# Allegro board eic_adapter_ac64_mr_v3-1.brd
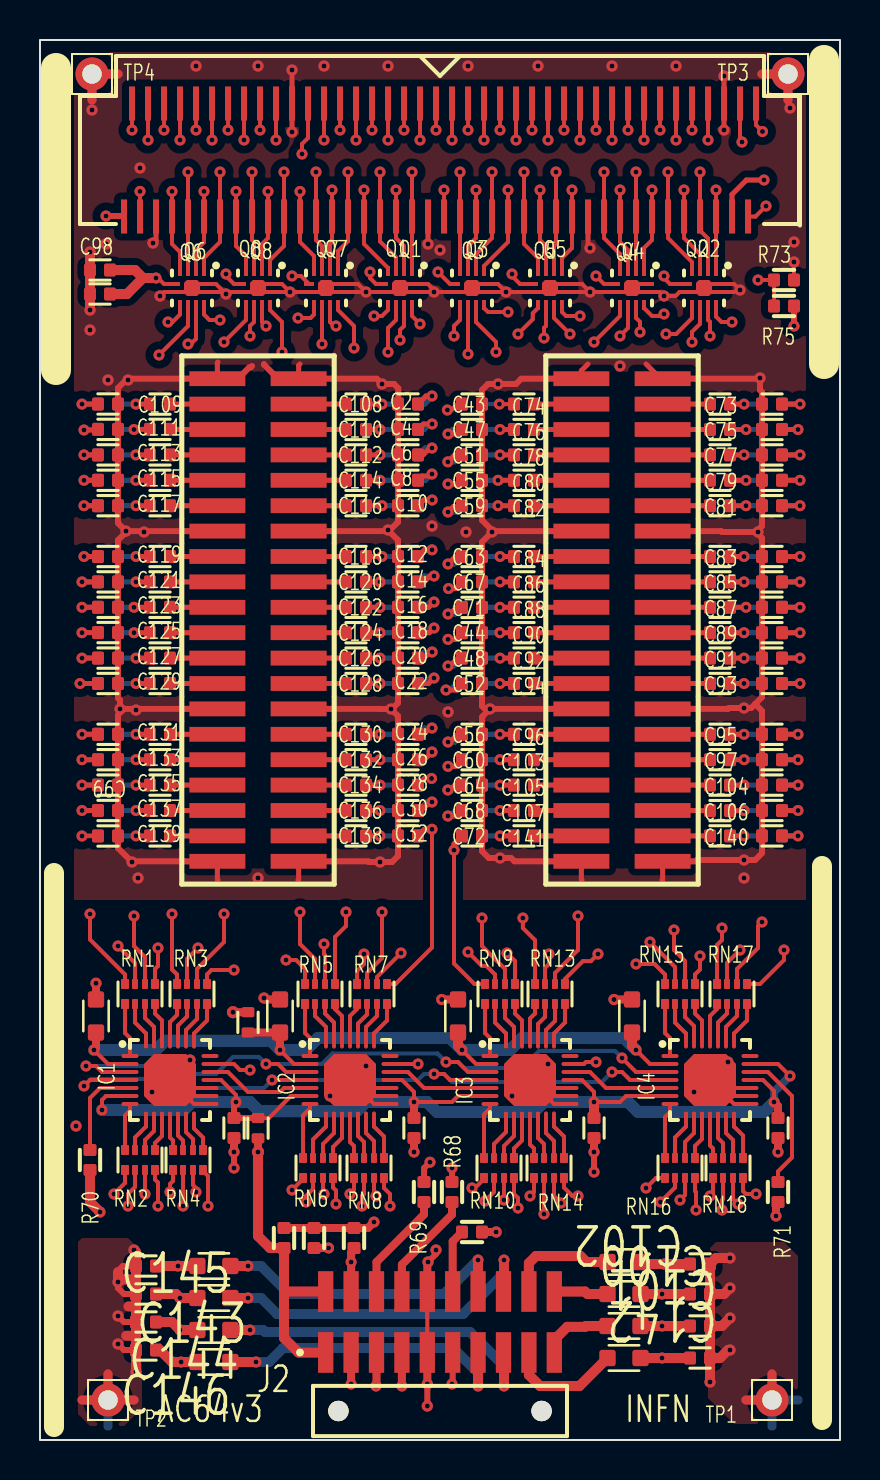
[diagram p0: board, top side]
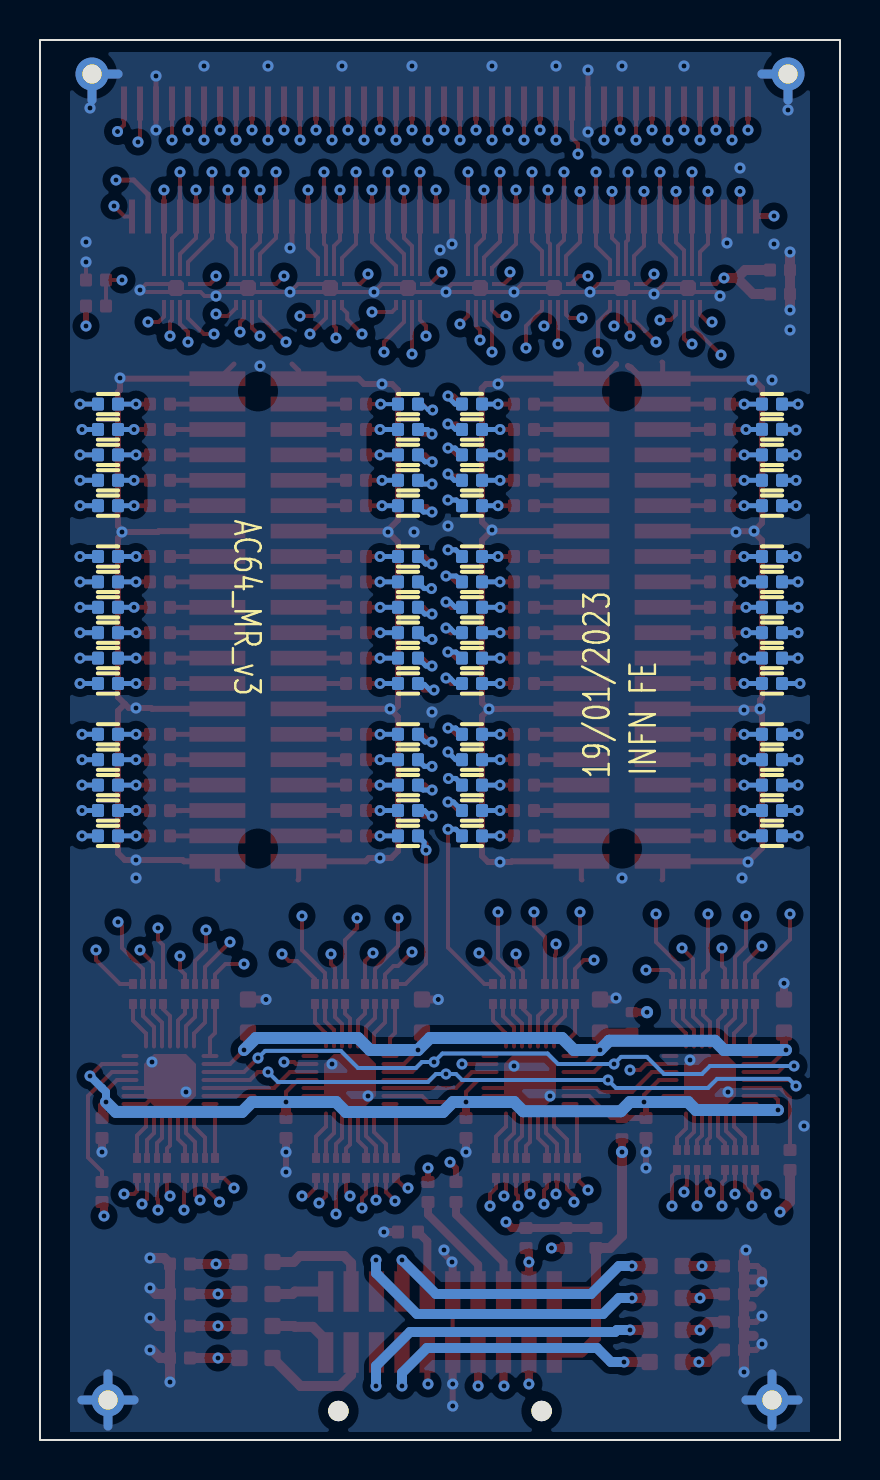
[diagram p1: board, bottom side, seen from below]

Outline 40 x 70 mm; copper layers: TOP, LAYER_1, LAYER_2, LAYER_3, LAYER_4, LAYER_5, LAYER_6, LAYER_7, LAYER_8, BOTTOM. Coordinates in mm from the lower left corner of the outline.
Outline path: rectangle 0,0 40,70

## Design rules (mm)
constraint set DEFAULT: pair gap 0.2

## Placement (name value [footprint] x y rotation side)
C1  100nF  [SM_C_0402_R]  3 57.3 0 top
C2  100nF  [SM_C_0402_R]  18.4 51.8 0 top
C3  100nF  [SM_C_0402_R]  3.4 51.8 180 top
C4  100nF  [SM_C_0402_R]  18.4 50.52 0 top
C5  100nF  [SM_C_0402_R]  3.4 50.53 180 top
C6  100nF  [SM_C_0402_R]  18.4 49.26 0 top
C7  100nF  [SM_C_0402_R]  3.4 49.26 180 top
C8  100nF  [SM_C_0402_R]  18.4 47.98 0 top
C9  100nF  [SM_C_0402_R]  3.4 47.98 180 top
C10  100nF  [SM_C_0402_R]  18.4 46.72 0 top
C11  100nF  [SM_C_0402_R]  3.4 46.72 180 top
C12  100nF  [SM_C_0402_R]  18.4 44.17 0 top
C13  100nF  [SM_C_0402_R]  3.4 44.17 180 top
C14  100nF  [SM_C_0402_R]  18.4 42.91 0 top
C15  100nF  [SM_C_0402_R]  3.4 42.91 180 top
C16  100nF  [SM_C_0402_R]  18.4 41.63 0 top
C17  100nF  [SM_C_0402_R]  3.4 41.63 180 top
C18  100nF  [SM_C_0402_R]  18.4 40.37 0 top
C19  100nF  [SM_C_0402_R]  3.4 40.37 180 top
C20  100nF  [SM_C_0402_R]  18.4 39.09 0 top
C21  100nF  [SM_C_0402_R]  3.4 39.09 180 top
C22  100nF  [SM_C_0402_R]  18.4 37.83 0 top
C23  100nF  [SM_C_0402_R]  3.4 37.83 180 top
C24  100nF  [SM_C_0402_R]  18.4 35.28 0 top
C25  100nF  [SM_C_0402_R]  3.4 35.28 180 top
C26  100nF  [SM_C_0402_R]  18.4 34.02 0 top
C27  100nF  [SM_C_0402_R]  3.4 34.02 180 top
C28  100nF  [SM_C_0402_R]  18.4 32.74 0 top
C29  100nF  [SM_C_0402_R]  3.4 32.74 180 top
C30  100nF  [SM_C_0402_R]  18.4 31.47 0 top
C31  100nF  [SM_C_0402_R]  3.4 31.48 180 top
C32  100nF  [SM_C_0402_R]  18.4 30.2 0 top
C33  1uF  [SM_C_0603]  20.9 21.2 270 top
C34  100nF  [SM_C_0402_R]  18.7 15.6 90 top
C35  100nF  [SM_C_0402_R]  9.7 15.6 90 top
C36  1uF  [SM_C_0603]  12 21.2 270 top
C37  1uF  [SM_C_0603]  29.6 21.2 270 top
C38  1uF  [SM_C_0603]  2.8 21.2 270 top
C39  100nF  [SM_C_0402_R]  36.6 51.8 0 top
C40  100nF  [SM_C_0402_R]  27.7 15.6 90 top
C41  100nF  [SM_C_0402_R]  36.9 15.6 90 top
C42  100nF  [SM_C_0402_R]  36.6 40.37 0 top
C43  100nF  [SM_C_0402_R]  21.6 51.8 180 top
C44  100nF  [SM_C_0402_R]  21.6 40.37 180 top
C45  100nF  [SM_C_0402_R]  36.6 50.52 0 top
C46  100nF  [SM_C_0402_R]  36.6 39.09 0 top
C47  100nF  [SM_C_0402_R]  21.6 50.52 180 top
C48  100nF  [SM_C_0402_R]  21.6 39.09 180 top
C49  100nF  [SM_C_0402_R]  36.6 49.26 0 top
C50  100nF  [SM_C_0402_R]  36.6 37.83 0 top
C51  100nF  [SM_C_0402_R]  21.6 49.26 180 top
C52  100nF  [SM_C_0402_R]  21.6 37.83 180 top
C53  100nF  [SM_C_0402_R]  36.6 47.98 0 top
C54  100nF  [SM_C_0402_R]  36.6 35.28 0 top
C55  100nF  [SM_C_0402_R]  21.6 47.98 180 top
C56  100nF  [SM_C_0402_R]  21.6 35.28 180 top
C57  100nF  [SM_C_0402_R]  36.6 46.72 0 top
C58  100nF  [SM_C_0402_R]  36.6 34.02 0 top
C59  100nF  [SM_C_0402_R]  21.6 46.72 180 top
C60  100nF  [SM_C_0402_R]  21.6 34.02 180 top
C61  100nF  [SM_C_0402_R]  36.6 44.17 0 top
C62  100nF  [SM_C_0402_R]  36.6 32.74 0 top
C63  100nF  [SM_C_0402_R]  21.6 44.17 180 top
C64  100nF  [SM_C_0402_R]  21.6 32.74 180 top
C65  100nF  [SM_C_0402_R]  36.6 42.91 0 top
C66  100nF  [SM_C_0402_R]  36.6 31.48 0 top
C67  100nF  [SM_C_0402_R]  21.6 42.91 180 top
C68  100nF  [SM_C_0402_R]  21.6 31.48 180 top
C69  100nF  [SM_C_0402_R]  36.6 41.63 0 top
C70  100nF  [SM_C_0402_R]  36.6 30.2 0 top
C71  100nF  [SM_C_0402_R]  21.6 41.63 180 top
C72  100nF  [SM_C_0402_R]  21.6 30.2 180 top
C73  4.7nF  [SM_C_0402_R]  34 51.8 0 top
C74  4.7nF  [SM_C_0402_R]  24.2 51.8 180 top
C75  4.7nF  [SM_C_0402_R]  34 50.52 0 top
C76  4.7nF  [SM_C_0402_R]  24.2 50.52 180 top
C77  4.7nF  [SM_C_0402_R]  34 49.26 0 top
C78  4.7nF  [SM_C_0402_R]  24.2 49.26 180 top
C79  4.7nF  [SM_C_0402_R]  34 47.98 0 top
C80  4.7nF  [SM_C_0402_R]  24.2 47.98 180 top
C81  4.7nF  [SM_C_0402_R]  34 46.72 0 top
C82  4.7nF  [SM_C_0402_R]  24.2 46.72 180 top
C83  4.7nF  [SM_C_0402_R]  34 44.17 0 top
C84  4.7nF  [SM_C_0402_R]  24.2 44.17 180 top
C85  4.7nF  [SM_C_0402_R]  34 42.91 0 top
C86  4.7nF  [SM_C_0402_R]  24.2 42.91 180 top
C87  4.7nF  [SM_C_0402_R]  34 41.63 0 top
C88  4.7nF  [SM_C_0402_R]  24.2 41.63 180 top
C89  4.7nF  [SM_C_0402_R]  34 40.37 0 top
C90  4.7nF  [SM_C_0402_R]  24.2 40.37 180 top
C91  4.7nF  [SM_C_0402_R]  34 39.09 0 top
C92  4.7nF  [SM_C_0402_R]  24.2 39.09 180 top
C93  4.7nF  [SM_C_0402_R]  34 37.83 0 top
C94  4.7nF  [SM_C_0402_R]  24.2 37.83 180 top
C95  4.7nF  [SM_C_0402_R]  34 35.28 0 top
C96  4.7nF  [SM_C_0402_R]  24.2 35.28 180 top
C97  4.7nF  [SM_C_0402_R]  34 34.02 0 top
C98  100nF  [SM_C_0402_R]  3 58.5 0 top
C99  100nF  [SM_C_0402_R]  3.4 30.2 180 top
C100  100nF  [SM_C_0402_R]  33 7.3 180 top
C101  100nF  [SM_C_0402_R]  33 5.7 180 top
C102  100nF  [SM_C_0402_R]  33 8.8 180 top
C103  4.7nF  [SM_C_0402_R]  24.2 34.02 180 top
C104  4.7nF  [SM_C_0402_R]  34 32.74 0 top
C105  4.7nF  [SM_C_0402_R]  24.2 32.74 180 top
C106  4.7nF  [SM_C_0402_R]  34 31.47 0 top
C107  4.7nF  [SM_C_0402_R]  24.2 31.48 180 top
C108  4.7nF  [SM_C_0402_R]  15.8 51.8 0 top
C109  4.7nF  [SM_C_0402_R]  6 51.8 180 top
C110  4.7nF  [SM_C_0402_R]  15.8 50.52 0 top
C111  4.7nF  [SM_C_0402_R]  6 50.53 180 top
C112  4.7nF  [SM_C_0402_R]  15.8 49.26 0 top
C113  4.7nF  [SM_C_0402_R]  6 49.26 180 top
C114  4.7nF  [SM_C_0402_R]  15.8 47.98 0 top
C115  4.7nF  [SM_C_0402_R]  6 47.98 180 top
C116  4.7nF  [SM_C_0402_R]  15.8 46.72 0 top
C117  4.7nF  [SM_C_0402_R]  6 46.72 180 top
C118  4.7nF  [SM_C_0402_R]  15.8 44.17 0 top
C119  4.7nF  [SM_C_0402_R]  6 44.17 180 top
C120  4.7nF  [SM_C_0402_R]  15.8 42.91 0 top
C121  4.7nF  [SM_C_0402_R]  6 42.91 180 top
C122  4.7nF  [SM_C_0402_R]  15.8 41.63 0 top
C123  4.7nF  [SM_C_0402_R]  6 41.63 180 top
C124  4.7nF  [SM_C_0402_R]  15.8 40.37 0 top
C125  4.7nF  [SM_C_0402_R]  6 40.37 180 top
C126  4.7nF  [SM_C_0402_R]  15.8 39.09 0 top
C127  4.7nF  [SM_C_0402_R]  6 39.09 180 top
C128  4.7nF  [SM_C_0402_R]  15.8 37.83 0 top
C129  4.7nF  [SM_C_0402_R]  6 37.83 180 top
C130  4.7nF  [SM_C_0402_R]  15.8 35.28 0 top
C131  4.7nF  [SM_C_0402_R]  6 35.28 180 top
C132  4.7nF  [SM_C_0402_R]  15.8 34.02 0 top
C133  4.7nF  [SM_C_0402_R]  6 34.02 180 top
C134  4.7nF  [SM_C_0402_R]  15.8 32.74 0 top
C135  4.7nF  [SM_C_0402_R]  6 32.74 180 top
C136  4.7nF  [SM_C_0402_R]  15.8 31.48 0 top
C137  4.7nF  [SM_C_0402_R]  6 31.48 180 top
C138  4.7nF  [SM_C_0402_R]  15.8 30.2 0 top
C139  4.7nF  [SM_C_0402_R]  6 30.2 180 top
C140  4.7nF  [SM_C_0402_R]  34 30.2 0 top
C141  4.7nF  [SM_C_0402_R]  24.2 30.2 180 top
C142  100nF  [SM_C_0402_R]  33 4.1 180 top
C143  100nF  [SM_C_0402_R]  5.3 7.3 0 top
C144  100nF  [SM_C_0402_R]  5.3 5.9 0 top
C145  100nF  [SM_C_0402_R]  5.3 8.7 0 top
C146  100nF  [SM_C_0402_R]  5.3 4.5 0 top
IC1  AD5674RBCPZ-1  [QFN29P4X4X]  6.5 18 0 top
IC2  AD5674RBCPZ-1  [QFN29P4X4X]  15.5 18 0 top
IC3  AD5674RBCPZ-1  [QFN29P4X4X]  24.5 18 0 top
IC4  AD5674RBCPZ-1  [QFN29P4X4X]  33.5 18 0 top
J1  SAMTEC FTS-120-02-dv-a  [FTS-120-X-DV-A]  29.1 41 270 top
J2  CON20A  [SAMTEC_FTSH-110-01-F-DH-A]  20 5.9 180 top
J3  SAMTEC FTS-120-02-dv-a  [FTS-120-X-DV-A]  10.9 41 270 top
J4  CON80  [CONN_HIROSE_FH30-80S-04]  20 64 270 top
L1  BLM15AX102SN1D  [SM_L_0603_R]  29.2 7.3 180 top
L2  BLM15AX102SN1D  [SM_L_0402_R]  10.9 15.59 270 top
L3  BLM15AX102SN1D  [SM_L_0402_R]  10.4 20.88 90 top
L4  BLM15AX102SN1D  [SM_L_0603_R]  29.2 5.7 180 top
L5  BLM15AX102SN1D  [SM_L_0603_R]  29.2 8.9 180 top
L6  BLM15AX102SN1D  [SM_L_0603_R]  29.2 4.1 180 top
L7  BLM15AX102SN1D  [SM_L_0603_R]  8.69 7.1 0 top
L8  BLM15AX102SN1D  [SM_L_0603_R]  8.69 5.5 0 top
L9  BLM15AX102SN1D  [SM_L_0603_R]  8.69 8.7 0 top
L10  BLM15AX102SN1D  [SM_L_0603_R]  8.69 3.9 0 top
NOREF  -  []  29.1 41 0 top
NOREF#2  -  []  10.9 41 0 top
NOREF#3  -  []  0 70 0 top
NOREF#4  -  []  20 64 90 top
NOREF#5  -  []  0 64.3 0 top
NOREF#6  -  []  0 0 90 top
NOREF#7  -  []  29.1 41 90 top
NOREF#8  -  []  0 0 0 top
Q1  DMN1250UFEL-7  [QFN13P1_50X1_50]  18 57.6 270 top
Q2  DMN1250UFEL-7  [QFN13P1_50X1_50]  33.2 57.6 270 top
Q3  DMN1250UFEL-7  [QFN13P1_50X1_50]  21.6 57.6 270 top
Q4  DMN1250UFEL-7  [QFN13P1_50X1_50]  29.6 57.6 270 top
Q5  DMN1250UFEL-7  [QFN13P1_50X1_50]  25.5 57.6 270 top
Q6  DMN1250UFEL-7  [QFN13P1_50X1_50]  7.6 57.6 270 top
Q7  DMN1250UFEL-7  [QFN13P1_50X1_50]  14.3 57.6 270 top
Q8  DMN1250UFEL-7  [QFN13P1_50X1_50]  10.9 57.6 270 top
R1  470ohm  [SM_R_0402_R]  18.4 51.8 180 bottom
R3  470ohm  [SM_R_0402_R]  18.4 40.37 180 bottom
R5  0ohm  [SM_R_0402_R]  12.2 10.1 90 top
R6  4.7K  [SM_R_0402]  15.7 10.1 270 top
R7  4.7K  [SM_R_0402]  13.7 10.1 270 top
R8  470ohm  [SM_R_0402_R]  3.4 51.8 0 bottom
R10  470ohm  [SM_R_0402_R]  3.4 40.37 0 bottom
R12  470ohm  [SM_R_0402_R]  18.4 50.52 180 bottom
R14  470ohm  [SM_R_0402_R]  18.4 39.09 180 bottom
R16  470ohm  [SM_R_0402_R]  3.4 50.53 0 bottom
R18  470ohm  [SM_R_0402_R]  3.4 39.09 0 bottom
R20  470ohm  [SM_R_0402_R]  18.4 49.26 180 bottom
R22  470ohm  [SM_R_0402_R]  18.4 37.83 180 bottom
R24  470ohm  [SM_R_0402_R]  3.4 49.26 0 bottom
R26  470ohm  [SM_R_0402_R]  3.4 37.83 0 bottom
R28  470ohm  [SM_R_0402_R]  18.4 47.98 180 bottom
R30  470ohm  [SM_R_0402_R]  18.4 35.28 180 bottom
R32  470ohm  [SM_R_0402_R]  3.4 47.98 0 bottom
R34  470ohm  [SM_R_0402_R]  3.4 35.28 0 bottom
R36  470ohm  [SM_R_0402_R]  18.4 46.72 180 bottom
R38  470ohm  [SM_R_0402_R]  18.4 34.02 180 bottom
R40  470ohm  [SM_R_0402_R]  3.4 46.72 0 bottom
R42  470ohm  [SM_R_0402_R]  3.4 34.02 0 bottom
R44  470ohm  [SM_R_0402_R]  18.4 44.17 180 bottom
R46  470ohm  [SM_R_0402_R]  18.4 32.74 180 bottom
R48  470ohm  [SM_R_0402_R]  3.4 44.17 0 bottom
R50  470ohm  [SM_R_0402_R]  3.4 32.74 0 bottom
R52  470ohm  [SM_R_0402_R]  18.4 42.91 180 bottom
R54  470ohm  [SM_R_0402_R]  18.4 31.48 180 bottom
R56  470ohm  [SM_R_0402_R]  3.4 42.91 0 bottom
R58  470ohm  [SM_R_0402_R]  3.4 31.48 0 bottom
R60  470ohm  [SM_R_0402_R]  18.4 41.63 180 bottom
R62  470ohm  [SM_R_0402_R]  18.4 30.2 180 bottom
R64  470ohm  [SM_R_0402_R]  3.4 41.63 0 bottom
R66  470ohm  [SM_R_0402_R]  3.4 30.21 0 bottom
R68  47ohm  [SM_R_0402_R]  20.6 12.4 270 top
R69  47ohm  [SM_R_0402_R]  19.2 12.4 270 top
R70  47ohm  [SM_R_0402_R]  2.5 14 270 top
R71  47ohm  [SM_R_0402_R]  36.9 12.4 270 top
R72  470ohm  [SM_R_0402_R]  36.6 51.8 180 bottom
R73  4.7K  [SM_R_0402_R]  37.2 58 0 top
R74  0ohm  [SM_R_0402_R]  21.6 10.4 180 top
R75  100ohm  [SM_R_0402_R]  37.2 56.7 0 top
R81  470ohm  [SM_R_0402_R]  36.6 40.37 180 bottom
R83  470ohm  [SM_R_0402_R]  21.6 51.8 0 bottom
R85  470ohm  [SM_R_0402_R]  21.6 40.37 0 bottom
R87  470ohm  [SM_R_0402_R]  36.6 50.52 180 bottom
R89  470ohm  [SM_R_0402_R]  36.6 39.09 180 bottom
R91  470ohm  [SM_R_0402_R]  21.6 50.52 0 bottom
R93  470ohm  [SM_R_0402_R]  21.6 39.09 0 bottom
R95  470ohm  [SM_R_0402_R]  36.6 49.26 180 bottom
R97  470ohm  [SM_R_0402_R]  36.6 37.83 180 bottom
R99  470ohm  [SM_R_0402_R]  21.6 49.26 0 bottom
R101  470ohm  [SM_R_0402_R]  21.6 37.83 0 bottom
R103  470ohm  [SM_R_0402_R]  36.6 47.98 180 bottom
R105  470ohm  [SM_R_0402_R]  36.6 35.28 180 bottom
R107  470ohm  [SM_R_0402_R]  21.6 47.98 0 bottom
R109  470ohm  [SM_R_0402_R]  21.6 35.28 0 bottom
R111  470ohm  [SM_R_0402_R]  36.6 46.72 180 bottom
R113  470ohm  [SM_R_0402_R]  36.6 34.02 180 bottom
R115  470ohm  [SM_R_0402_R]  21.6 46.72 0 bottom
R117  470ohm  [SM_R_0402_R]  21.6 34.02 0 bottom
R119  470ohm  [SM_R_0402_R]  36.6 44.17 180 bottom
R121  470ohm  [SM_R_0402_R]  36.6 32.74 180 bottom
R123  470ohm  [SM_R_0402_R]  21.6 44.17 0 bottom
R125  470ohm  [SM_R_0402_R]  21.6 32.74 0 bottom
R127  470ohm  [SM_R_0402_R]  36.6 42.91 180 bottom
R129  470ohm  [SM_R_0402_R]  36.6 31.48 180 bottom
R131  470ohm  [SM_R_0402_R]  21.6 42.91 0 bottom
R133  470ohm  [SM_R_0402_R]  21.6 31.48 0 bottom
R135  470ohm  [SM_R_0402_R]  36.6 41.63 180 bottom
R137  470ohm  [SM_R_0402_R]  36.6 30.2 180 bottom
R139  470ohm  [SM_R_0402_R]  21.6 41.63 0 bottom
R141  470ohm  [SM_R_0402_R]  21.6 30.2 0 bottom
RN1  47ohm x 4  [ARRAY_CAY10-J4_8P]  5 22.3 0 top
RN2  47ohm x 4  [ARRAY_CAY10-J4_8P]  5 14 180 top
RN3  47ohm x 4  [ARRAY_CAY10-J4_8P]  7.6 22.3 0 top
RN4  47ohm x 4  [ARRAY_CAY10-J4_8P]  7.4 14 180 top
RN5  47ohm x 4  [ARRAY_CAY10-J4_8P]  14 22.3 0 top
RN6  47ohm x 4  [ARRAY_CAY10-J4_8P]  13.9 13.6 180 top
RN7  47ohm x 4  [ARRAY_CAY10-J4_8P]  16.6 22.3 0 top
RN8  47ohm x 4  [ARRAY_CAY10-J4_8P]  16.45 13.6 180 top
RN9  47ohm x 4  [ARRAY_CAY10-J4_8P]  23 22.3 0 top
RN10  47ohm x 4  [ARRAY_CAY10-J4_8P]  22.95 13.6 180 top
RN13  47ohm x 4  [ARRAY_CAY10-J4_8P]  25.5 22.3 0 top
RN14  47ohm x 4  [ARRAY_CAY10-J4_8P]  25.45 13.6 180 top
RN15  47ohm x 4  [ARRAY_CAY10-J4_8P]  32 22.3 0 top
RN16  47ohm x 4  [ARRAY_CAY10-J4_8P]  32 13.6 180 top
RN17  47ohm x 4  [ARRAY_CAY10-J4_8P]  34.6 22.3 0 top
RN18  47ohm x 4  [ARRAY_CAY10-J4_8P]  34.4 13.6 180 top
TP1  TP  [PIN]  36.6 2 0 top
TP2  TP  [PIN]  3.4 2 0 top
TP3  TP  [PIN]  37.4 68.3 0 top
TP4  TP  [PIN]  2.6 68.3 0 top

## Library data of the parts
C1-C72 C98-C102 C142-C146 = C-100nF
C73-C97 C103-C141 = C
IC1-IC4 = AD5674RBCPZ
J1 J3 = FTSH-120-03-F-DV
J2 = CON20A
J4 = CON80
L1-L10 = BEAD_SM0603
Q1-Q8 = DMN1250UFEL-7
R1 R3 R5-R8 R10 R12 R14 R16 R18 R20 R22 R24 R26 R28 R30 R32 R34 R36 R38 R40 R42 R44 R46 R48 R50 R52 R54 R56 R58 R60 R62 R64 R66 R68-R75 R81 R83 R85 R87 R89 R91 R93 R95 R97 R99 R101 R103 R105 R107 R109 R111 R113 R115 R117 R119 R121 R123 R125 R127 R129 R131 R133 R135 R137 R139 R141 = R
RN1-RN10 RN13-RN18 = RES_ISO8
TP1-TP4 = TP

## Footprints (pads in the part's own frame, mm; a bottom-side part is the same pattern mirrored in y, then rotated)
ARRAY_CAY10-J4_8P
  rrect 0.4x0.5 smd: 1(-0.75,-0.5) 4(0.75,-0.5) 5(0.75,0.5) 8(-0.75,0.5)
  rrect 0.3x0.5 smd: 2(-0.25,-0.5) 3(0.25,-0.5) 6(0.25,0.5) 7(-0.25,0.5)
CONN_HIROSE_FH30-80S-04
  rect 1.7x0.3 smd: 1(-2.825,15.8) 2(2.825,15.4) 3(-2.825,15) 4(2.825,14.6) 5(-2.825,14.2) 6(2.825,13.8) 7(-2.825,13.4) 8(2.825,13) 9(-2.825,12.6) 10(2.825,12.2) 11(-2.825,11.8) 12(2.825,11.4) 13(-2.825,11) 14(2.825,10.6) 15(-2.825,10.2) 16(2.825,9.8) 17(-2.825,9.4) 18(2.825,9) 19(-2.825,8.6) 20(2.825,8.2) 21(-2.825,7.8) 22(2.825,7.4) 23(-2.825,7) 24(2.825,6.6) 25(-2.825,6.2) 26(2.825,5.8) 27(-2.825,5.4) 28(2.825,5) 29(-2.825,4.6) 30(2.825,4.2) 31(-2.825,3.8) 32(2.825,3.4) 33(-2.825,3) 34(2.825,2.6) 35(-2.825,2.2) 36(2.825,1.8) 37(-2.825,1.4) 38(2.825,1) 39(-2.825,0.6) 40(2.825,0.2) 41(-2.825,-0.2) 42(2.825,-0.6) 43(-2.825,-1) 44(2.825,-1.4) 45(-2.825,-1.8) 46(2.825,-2.2) 47(-2.825,-2.6) 48(2.825,-3) 49(-2.825,-3.4) 50(2.825,-3.8) 51(-2.825,-4.2) 52(2.825,-4.6) 53(-2.825,-5) 54(2.825,-5.4) 55(-2.825,-5.8) 56(2.825,-6.2) 57(-2.825,-6.6) 58(2.825,-7) 59(-2.825,-7.4) 60(2.825,-7.8) 61(-2.825,-8.2) 62(2.825,-8.6) 63(-2.825,-9) 64(2.825,-9.4) 65(-2.825,-9.8) 66(2.825,-10.2) 67(-2.825,-10.6) 68(2.825,-11) 69(-2.825,-11.4) 70(2.825,-11.8) 71(-2.825,-12.2) 72(2.825,-12.6) 73(-2.825,-13) 74(2.825,-13.4) 75(-2.825,-13.8) 76(2.825,-14.2) 77(-2.825,-14.6) 78(2.825,-15) 79(-2.825,-15.4) 80(2.825,-15.8)
FTS-120-X-DV-A
  round 0 hole 1 unplated: (-11.43,0) (11.43,0)
  rect 0.737x2.794 smd: 1(-12.065,-2.032) 2(-12.065,2.032) 3(-10.795,-2.032) 4(-10.795,2.032) 5(-9.525,-2.032) 6(-9.525,2.032) 7(-8.255,-2.032) 8(-8.255,2.032) 9(-6.985,-2.032) 10(-6.985,2.032) 11(-5.715,-2.032) 12(-5.715,2.032) 13(-4.445,-2.032) 14(-4.445,2.032) 15(-3.175,-2.032) 16(-3.175,2.032) 17(-1.905,-2.032) 18(-1.905,2.032) 19(-0.635,-2.032) 20(-0.635,2.032) 21(0.635,-2.032) 22(0.635,2.032) 23(1.905,-2.032) 24(1.905,2.032) 25(3.175,-2.032) 26(3.175,2.032) 27(4.445,-2.032) 28(4.445,2.032) 29(5.715,-2.032) 30(5.715,2.032) 31(6.985,-2.032) 32(6.985,2.032) 33(8.255,-2.032) 34(8.255,2.032) 35(9.525,-2.032) 36(9.525,2.032) 37(10.795,-2.032) 38(10.795,2.032) 39(12.065,-2.032) 40(12.065,2.032)
PIN
  round 1.651 hole 0.965: 1(0,0)
QFN13P1_50X1_50
  rect 0.5x0.2 smd: 1(-0.85,0.6) 2(-0.85,0.2) 3(-0.85,-0.2) 4(-0.85,-0.6) 7(0.85,-0.6) 8(0.85,-0.2) 9(0.85,0.2) 10(0.85,0.6)
  rect 0.2x0.5 smd: 5(-0.2,-0.85) 6(0.2,-0.85) 11(0.2,0.85) 12(-0.2,0.85)
  rrect 0.8x0.8 smd: 13(0,0)
QFN29P4X4X
  rrect 0.85x0.2 smd: 1(-2,1.2) 2(-2,0.8) 3(-2,0.4) 4(-2,0) 5(-2,-0.4) 6(-2,-0.8) 7(-2,-1.2) 15(2,-1.2) 16(2,-0.8) 17(2,-0.4) 18(2,0) 19(2,0.4) 20(2,0.8) 21(2,1.2)
  rrect 0.2x0.85 smd: 8(-1.2,-2) 9(-0.8,-2) 10(-0.4,-2) 11(0,-2) 12(0.4,-2) 13(0.8,-2) 14(1.2,-2) 22(1.2,2) 23(0.8,2) 24(0.4,2) 25(0,2) 26(-0.4,2) 27(-0.8,2) 28(-1.2,2)
  rrect 2.6x2.6 smd: 29(0,0)
SAMTEC_FTSH-110-01-F-DH-A
  round 1.02 hole 1.02 unplated: (-5.08,4.45) (5.08,4.45)
  rect 0.76x2.03 smd: 1(5.715,1.525) 2(5.715,-1.525) 3(4.445,1.525) 4(4.445,-1.525) 5(3.175,1.525) 6(3.175,-1.525) 7(1.905,1.525) 8(1.905,-1.525) 9(0.635,1.525) 10(0.635,-1.525) 11(-0.635,1.525) 12(-0.635,-1.525) 13(-1.905,1.525) 14(-1.905,-1.525) 15(-3.175,1.525) 16(-3.175,-1.525) 17(-4.445,1.525) 18(-4.445,-1.525) 19(-5.715,1.525) 20(-5.715,-1.525)
SM_C_0402_R
  rrect 0.6x0.65 smd: 1(-0.5,0) 2(0.5,0)
SM_C_0603
  rrect 0.813x0.813 smd: 1(-0.826,0) 2(0.826,0)
SM_L_0402_R
  rrect 0.51x0.635 smd: 1(-0.508,0) 2(0.508,0)
SM_L_0603_R
  rrect 0.813x0.813 smd: 1(-0.826,0) 2(0.826,0)
SM_R_0402
  rrect 0.6x0.65 smd: 1(-0.5,0) 2(0.5,0)
SM_R_0402_R
  rrect 0.6x0.65 smd: 1(-0.5,0) 2(0.5,0)

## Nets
+5V: J2.1 J2.2 L2.2 L3.2 R5.1
VDD_DACS: C33.2 C36.2 C37.2 C38.2 IC1.2 IC2.2 IC3.2 IC4.2 L3.1
0: C1.1 C2.1 C3.1 C4.1 C5.1 C6.1 C7.1 C8.1 C9.1 C10.1 C11.1 C12.1 C13.1 C14.1 C15.1 C16.1 C17.1 C18.1 C19.1 C20.1 C21.1 C22.1 C23.1 C24.1 C25.1 C26.1 C27.1 C28.1 C29.1 C30.1 C31.1 C32.1 C33.1 C34.1 C35.1 C36.1 C37.1 C38.1 C39.1 C40.1 C41.1 C42.1 C43.1 C44.1 C45.1 C46.1 C47.1 C48.1 C49.1 C50.1 C51.1 C52.1 C53.1 C54.1 C55.1 C56.1 C57.1 C58.1 C59.1 C60.1 C61.1 C62.1 C63.1 C64.1 C65.1 C66.1 C67.1 C68.1 C69.1 C70.1 C71.1 C72.1 C98.1 C99.1 C100.1 C101.1 C102.1 C142.1 C143.1 C144.1 C145.1 C146.1 IC1.15 IC1.16 IC1.17 IC1.29 IC2.15 IC2.16 IC2.17 IC2.29 IC3.15 IC3.16 IC3.17 IC3.29 IC4.15 IC4.16 IC4.17 IC4.29 J1.1 J1.2 J1.13 J1.14 J1.27 J1.28 J1.39 J1.40 J2.9 J2.10 J3.1 J3.2 J3.13 J3.14 J3.27 J3.28 J3.39 J3.40 J4.5 J4.22 J4.42 J4.59 J4.76 Q1.6 Q1.11 Q1.12 Q1.13(S_4) Q2.6 Q2.11 Q2.12 Q2.13(S_4) Q3.6 Q3.11 Q3.12 Q3.13(S_4) Q4.6 Q4.11 Q4.12 Q4.13(S_4) Q5.6 Q5.11 Q5.12 Q5.13(S_4) Q6.6 Q6.11 Q6.12 Q6.13(S_4) Q7.6 Q7.11 Q7.12 Q7.13(S_4) Q8.6 Q8.11 Q8.12 Q8.13(S_4) R73.2 R74.1 TP1.1 TP2.1 TP3.1 TP4.1
/LD: J2.8 R68.2
ALCOR_IN0: C108.1 J3.4
ALCOR_IN1: C109.1 J3.3
ALCOR_IN2: C110.1 J3.6
ALCOR_IN3: C111.1 J3.5
ALCOR_IN4: C112.1 J3.8
ALCOR_IN5: C113.1 J3.7
ALCOR_IN6: C114.1 J3.10
ALCOR_IN7: C115.1 J3.9
ALCOR_IN8: C116.1 J3.12
ALCOR_IN9: C117.1 J3.11
ALCOR_IN10: C118.1 J3.16
ALCOR_IN11: C119.1 J3.15
ALCOR_IN12: C120.1 J3.18
ALCOR_IN13: C121.1 J3.17
ALCOR_IN14: C122.1 J3.20
ALCOR_IN15: C123.1 J3.19
ALCOR_IN16: C124.1 J3.22
ALCOR_IN17: C125.1 J3.21
ALCOR_IN18: C126.1 J3.24
ALCOR_IN19: C127.1 J3.23
ALCOR_IN20: C128.1 J3.26
ALCOR_IN21: C129.1 J3.25
ALCOR_IN22: C130.1 J3.30
ALCOR_IN23: C131.1 J3.29
ALCOR_IN24: C132.1 J3.32
ALCOR_IN25: C133.1 J3.31
ALCOR_IN26: C134.1 J3.34
ALCOR_IN27: C135.1 J3.33
ALCOR_IN28: C136.1 J3.36
ALCOR_IN29: C137.1 J3.35
ALCOR_IN30: C138.1 J3.38
ALCOR_IN31: C139.1 J3.37
ALCOR_IN32: C73.1 J1.4
ALCOR_IN33: C74.1 J1.3
ALCOR_IN34: C75.1 J1.6
ALCOR_IN35: C76.1 J1.5
ALCOR_IN36: C77.1 J1.8
ALCOR_IN37: C78.1 J1.7
ALCOR_IN38: C79.1 J1.10
ALCOR_IN39: C80.1 J1.9
ALCOR_IN40: C81.1 J1.12
ALCOR_IN41: C82.1 J1.11
ALCOR_IN42: C83.1 J1.16
ALCOR_IN43: C84.1 J1.15
ALCOR_IN44: C85.1 J1.18
ALCOR_IN45: C86.1 J1.17
ALCOR_IN46: C87.1 J1.20
ALCOR_IN47: C88.1 J1.19
ALCOR_IN48: C89.1 J1.22
ALCOR_IN49: C90.1 J1.21
ALCOR_IN50: C91.1 J1.24
ALCOR_IN51: C92.1 J1.23
ALCOR_IN52: C93.1 J1.26
ALCOR_IN53: C94.1 J1.25
ALCOR_IN54: C95.1 J1.30
ALCOR_IN55: C96.1 J1.29
ALCOR_IN56: C97.1 J1.32
ALCOR_IN57: C103.1 J1.31
ALCOR_IN58: C104.1 J1.34
ALCOR_IN59: C105.1 J1.33
ALCOR_IN60: C106.1 J1.36
ALCOR_IN61: C107.1 J1.35
ALCOR_IN62: C140.1 J1.38
ALCOR_IN63: C141.1 J1.37
ANNEALING_ON: J2.11 R75.2
DIN: J2.5 R70.2
DOUT: J2.7 R71.2
EN_ANNEALING: C1.2 C98.2 Q1.5 Q2.5 Q3.5 Q4.5 Q5.5 Q6.5 Q7.5 Q8.5 R73.1 R75.1
LM73SCL: J2.4 J4.40 R6.2
LM73SDA: J2.3 J4.41 R7.2
LM73VCC: J4.39 R5.2 R6.1 R7.1
SCK: J2.6 R69.2
SIPMOUT0: C108.2 J4.43 Q1.10 R1.2
SIPMOUT1: C109.2 J4.75 Q6.7 R8.2
SIPMOUT2: C110.2 J4.44 Q1.1 R12.2
SIPMOUT3: C111.2 J4.74 Q6.4 R16.2
SIPMOUT4: C112.2 J4.45 Q1.9 R20.2
SIPMOUT5: C113.2 J4.73 Q6.8 R24.2
SIPMOUT6: C114.2 J4.46 Q1.2 R28.2
SIPMOUT7: C115.2 J4.72 Q6.3 R32.2
SIPMOUT8: C116.2 J4.47 Q1.8 R36.2
SIPMOUT9: C117.2 J4.71 Q6.9 R40.2
SIPMOUT10: C118.2 J4.48 Q1.3 R44.2
SIPMOUT11: C119.2 J4.70 Q6.2 R48.2
SIPMOUT12: C120.2 J4.49 Q1.7 R52.2
SIPMOUT13: C121.2 J4.69 Q6.10 R56.2
SIPMOUT14: C122.2 J4.50 Q1.4 R60.2
SIPMOUT15: C123.2 J4.68 Q6.1 R64.2
SIPMOUT16: C124.2 J4.51 Q7.10 R3.2
SIPMOUT17: C125.2 J4.67 Q8.7 R10.2
SIPMOUT18: C126.2 J4.52 Q7.1 R14.2
SIPMOUT19: C127.2 J4.66 Q8.4 R18.2
SIPMOUT20: C128.2 J4.53 Q7.9 R22.2
SIPMOUT21: C129.2 J4.65 Q8.8 R26.2
SIPMOUT22: C130.2 J4.54 Q7.2 R30.2
SIPMOUT23: C131.2 J4.64 Q8.3 R34.2
SIPMOUT24: C132.2 J4.55 Q7.8 R38.2
SIPMOUT25: C133.2 J4.63 Q8.9 R42.2
SIPMOUT26: C134.2 J4.56 Q7.3 R46.2
SIPMOUT27: C135.2 J4.62 Q8.2 R50.2
SIPMOUT28: C136.2 J4.57 Q7.7 R54.2
SIPMOUT29: C137.2 J4.61 Q8.10 R58.2
SIPMOUT30: C138.2 J4.58 Q7.4 R62.2
SIPMOUT31: C139.2 J4.60 Q8.1 R66.2
SIPMOUT32: C73.2 J4.6 Q2.1 R72.2
SIPMOUT33: C74.2 J4.38 Q3.4 R83.2
SIPMOUT34: C75.2 J4.7 Q2.10 R87.2
SIPMOUT35: C76.2 J4.37 Q3.7 R91.2
SIPMOUT36: C77.2 J4.8 Q2.2 R95.2
SIPMOUT37: C78.2 J4.36 Q3.3 R99.2
SIPMOUT38: C79.2 J4.9 Q2.9 R103.2
SIPMOUT39: C80.2 J4.35 Q3.8 R107.2
SIPMOUT40: C81.2 J4.10 Q2.3 R111.2
SIPMOUT41: C82.2 J4.34 Q3.2 R115.2
SIPMOUT42: C83.2 J4.11 Q2.8 R119.2
SIPMOUT43: C84.2 J4.33 Q3.9 R123.2
SIPMOUT44: C85.2 J4.12 Q2.4 R127.2
SIPMOUT45: C86.2 J4.32 Q3.1 R131.2
SIPMOUT46: C87.2 J4.13 Q2.7 R135.2
SIPMOUT47: C88.2 J4.31 Q3.10 R139.2
SIPMOUT48: C89.2 J4.14 Q4.1 R81.2
SIPMOUT49: C90.2 J4.30 Q5.4 R85.2
SIPMOUT50: C91.2 J4.15 Q4.10 R89.2
SIPMOUT51: C92.2 J4.29 Q5.7 R93.2
SIPMOUT52: C93.2 J4.16 Q4.2 R97.2
SIPMOUT53: C94.2 J4.28 Q5.3 R101.2
SIPMOUT54: C95.2 J4.17 Q4.9 R105.2
SIPMOUT55: C96.2 J4.27 Q5.8 R109.2
SIPMOUT56: C97.2 J4.18 Q4.3 R113.2
SIPMOUT57: C103.2 J4.26 Q5.2 R117.2
SIPMOUT58: C104.2 J4.19 Q4.8 R121.2
SIPMOUT59: C105.2 J4.25 Q5.9 R125.2
SIPMOUT60: C106.2 J4.20 Q4.4 R129.2
SIPMOUT61: C107.2 J4.24 Q5.1 R133.2
SIPMOUT62: C140.2 J4.21 Q4.7 R137.2
SIPMOUT63: C141.2 J4.23 Q5.10 R141.2
VB0: C100.2 J4.1 L1.1
VB1: C101.2 J4.2 L4.1
VB2: C102.2 J4.3 L5.1
VB3: C142.2 J4.4 L6.1
VB4: C143.2 J4.77 L7.1
VB5: C144.2 J4.78 L8.1
VB6: C145.2 J4.79 L9.1
VB7: C146.2 J4.80 L10.1
VBIAS_0: J2.20 L1.2
VBIAS_1: J2.19 L4.2
VBIAS_2: J2.18 L5.2
VBIAS_3: J2.17 L6.2
VBIAS_4: J2.16 L7.2
VBIAS_5: J2.15 L8.2
VBIAS_6: J2.14 L9.2
VBIAS_7: J2.13 L10.2
VLOGIC: C34.2 C35.2 C40.2 C41.2 IC1.6 IC1.18 IC1.20 IC2.6 IC2.18 IC2.20 IC3.6 IC3.18 IC3.20 IC4.6 IC4.18 IC4.20 L2.1
VTRIM-0: C2.2 R1.1 RN6.5
VTRIM-1: C3.2 R8.1 RN3.5
VTRIM-2: C4.2 R12.1 RN5.8
VTRIM-3: C5.2 R16.1 RN4.8
VTRIM-4: C6.2 R20.1 RN6.6
VTRIM-5: C7.2 R24.1 RN3.6
VTRIM-6: C8.2 R28.1 RN5.7
VTRIM-7: C9.2 R32.1 RN4.7
VTRIM-8: C10.2 R36.1 RN6.7
VTRIM-9: C11.2 R40.1 RN3.7
VTRIM-10: C12.2 R44.1 RN5.6
VTRIM-11: C13.2 R48.1 RN4.6
VTRIM-12: C14.2 R52.1 RN6.8
VTRIM-13: C15.2 R56.1 RN3.8
VTRIM-14: C16.2 R60.1 RN5.5
VTRIM-15: C17.2 R64.1 RN4.5
VTRIM-16: C18.2 R3.1 RN8.5
VTRIM-17: C19.2 R10.1 RN1.5
VTRIM-18: C20.2 R14.1 RN7.8
VTRIM-19: C21.2 R18.1 RN2.8
VTRIM-20: C22.2 R22.1 RN8.6
VTRIM-21: C23.2 R26.1 RN1.6
VTRIM-22: C24.2 R30.1 RN7.7
VTRIM-23: C25.2 R34.1 RN2.7
VTRIM-24: C26.2 R38.1 RN8.7
VTRIM-25: C27.2 R42.1 RN1.7
VTRIM-26: C28.2 R46.1 RN7.6
VTRIM-27: C29.2 R50.1 RN2.6
VTRIM-28: C30.2 R54.1 RN8.8
VTRIM-29: C31.2 R58.1 RN1.8
VTRIM-30: C32.2 R62.1 RN7.5
VTRIM-31: C99.2 R66.1 RN2.5
VTRIM-32: C39.2 R72.1 RN15.8
VTRIM-33: C43.2 R83.1 RN14.8
VTRIM-34: C45.2 R87.1 RN16.5
VTRIM-35: C47.2 R91.1 RN13.5
VTRIM-36: C49.2 R95.1 RN15.7
VTRIM-37: C51.2 R99.1 RN14.7
VTRIM-38: C53.2 R103.1 RN16.6
VTRIM-39: C55.2 R107.1 RN13.6
VTRIM-40: C57.2 R111.1 RN15.6
VTRIM-41: C59.2 R115.1 RN14.6
VTRIM-42: C61.2 R119.1 RN16.7
VTRIM-43: C63.2 R123.1 RN13.7
VTRIM-44: C65.2 R127.1 RN15.5
VTRIM-45: C67.2 R131.1 RN14.5
VTRIM-46: C69.2 R135.1 RN16.8
VTRIM-47: C71.2 R139.1 RN13.8
VTRIM-48: C42.2 R81.1 RN17.8
VTRIM-49: C44.2 R85.1 RN10.8
VTRIM-50: C46.2 R89.1 RN18.5
VTRIM-51: C48.2 R93.1 RN9.5
VTRIM-52: C50.2 R97.1 RN17.7
VTRIM-53: C52.2 R101.1 RN10.7
VTRIM-54: C54.2 R105.1 RN18.6
VTRIM-55: C56.2 R109.1 RN9.6
VTRIM-56: C58.2 R113.1 RN17.6
VTRIM-57: C60.2 R117.1 RN10.6
VTRIM-58: C62.2 R121.1 RN18.7
VTRIM-59: C64.2 R125.1 RN9.7
VTRIM-60: C66.2 R129.1 RN17.5
VTRIM-61: C68.2 R133.1 RN10.5
VTRIM-62: C70.2 R137.1 RN18.8
VTRIM-63: C72.2 R141.1 RN9.8
N919474: IC1.19 IC2.5
N920822: IC1.3 IC2.3 IC3.3 IC4.3 R68.1
N920826: IC1.4 IC2.4 IC3.4 IC4.4 R69.1
N920834: IC2.19 IC3.5
N924645: IC3.19 IC4.5
N924657: IC4.19 R71.1
N1004615: IC1.5 R70.1
N1031796: J2.12 R74.2
N1175823: IC1.14 RN4.1
N1175825: IC1.13 RN4.2
N1175827: IC1.12 RN4.3
N1175829: IC1.11 RN4.4
N1175847: IC1.25 RN3.1
N1175849: IC1.24 RN3.2
N1175851: IC1.23 RN3.3
N1175853: IC1.22 RN3.4
N1175887: IC1.10 RN2.1
N1175889: IC1.9 RN2.2
N1175891: IC1.8 RN2.3
N1175893: IC1.7 RN2.4
N1175919: IC1.1 RN1.1
N1175921: IC1.28 RN1.2
N1175923: IC1.27 RN1.3
N1175925: IC1.26 RN1.4
N1178151: IC2.25 RN7.1
N1178153: IC2.24 RN7.2
N1178155: IC2.23 RN7.3
N1178157: IC2.22 RN7.4
N1178159: IC2.10 RN6.1
N1178161: IC2.9 RN6.2
N1178163: IC2.8 RN6.3
N1178165: IC2.7 RN6.4
N1178167: IC2.14 RN8.1
N1178169: IC2.13 RN8.2
N1178171: IC2.12 RN8.3
N1178173: IC2.11 RN8.4
N1178175: IC2.1 RN5.1
N1178177: IC2.28 RN5.2
N1178179: IC2.27 RN5.3
N1178181: IC2.26 RN5.4
N1179923: IC3.10 RN10.1
N1179925: IC3.9 RN10.2
N1179927: IC3.8 RN10.3
N1179929: IC3.7 RN10.4
N1179931: IC3.14 RN14.1
N1179933: IC3.13 RN14.2
N1179935: IC3.12 RN14.3
N1179937: IC3.11 RN14.4
N1179939: IC3.1 RN9.1
N1179941: IC3.28 RN9.2
N1179943: IC3.27 RN9.3
N1179945: IC3.26 RN9.4
N1179947: IC3.25 RN13.1
N1179949: IC3.24 RN13.2
N1179951: IC3.23 RN13.3
N1179953: IC3.22 RN13.4
N1180213: IC4.14 RN18.1
N1180215: IC4.13 RN18.2
N1180217: IC4.12 RN18.3
N1180219: IC4.11 RN18.4
N1180221: IC4.1 RN15.1
N1180223: IC4.28 RN15.2
N1180225: IC4.27 RN15.3
N1180227: IC4.26 RN15.4
N1180229: IC4.25 RN17.1
N1180231: IC4.24 RN17.2
N1180233: IC4.23 RN17.3
N1180235: IC4.22 RN17.4
N1180237: IC4.10 RN16.1
N1180239: IC4.9 RN16.2
N1180241: IC4.8 RN16.3
N1180243: IC4.7 RN16.4

Pads without a net: IC1 21; IC2 21; IC3 21; IC4 21

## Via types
v1: diameter 0.55, hole 0.25, TOP to BOTTOM, 355 vias
v2: diameter 0.61, hole 0.254, TOP to BOTTOM, 2 vias
v3: diameter 0.559, hole 0.254, TOP to BOTTOM, 94 vias

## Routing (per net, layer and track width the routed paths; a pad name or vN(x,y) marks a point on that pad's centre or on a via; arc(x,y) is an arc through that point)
+5V: length 24.3
  TOP w0.4: v2(10.9,14.4) L2.2 ; L3.2 v2(9.65,21.39)
  TOP w0.5: 14.29,7.42 12.2,7.42 ; 12.2,7.42 12.2,5.1 12.93,4.38 J2.1 ; 12.2,7.42 R5.1 11.5,9.6 10.9,10.2 v2(10.9,14.4)
  LAYER_8 w0.5: v2(9.65,21.39) 9.65,19.85 8.9,19.1 8.9,16.4 v2(10.9,14.4)
VDD_DACS: length 41.3
  TOP w0.2: IC1.2 3.4,18.8 v1(2.7,19.5) ; v1(12,19.5) 12.7,18.8 IC2.2 ; IC3.2 21.8,18.8 v1(21.1,19.5) ; v1(29.8,19.5) 30.5,18.8 IC4.2
  TOP w0.4: C38.2 2.8,19.6 v1(2.7,19.5) ; v1(12,19.5) C36.2 L3.1
  TOP w0.5: C33.2 20.9,19.7 v1(21.1,19.5) ; C37.2 29.6,19.7 v1(29.8,19.5)
  BOTTOM w0.6: v1(2.7,19.5) 5.8,19.5 6.26,19.96 11.54,19.96 v1(12,19.5) 13.3,19.5 13.9,20.1 20.5,20.1 v1(21.1,19.5) 23.5,19.5 24.1,20.1 29.2,20.1 v1(29.8,19.5)
0: length 406.1
  TOP w0.2: IC3.16 25.5,17.2 25.4,17.1 ; Q3.13 21.8,57.4 Q3.11 v3(23.3,57.4) ; Q3.13 21.4,57.4 Q3.6 v3(19.7,57.4) ; Q3.13 21.8,57.8 Q3.12 22.9,57.8 v3(23.3,57.4) ; 7.4,17.1 7.5,17.2 IC1.16 ; 7.4,17.1 7.7,16.8 IC1.15 ; 7.4,17.1 7,17.5 ; 16,17.5 16.1,17.6 IC2.17 ; 16,17.5 IC2.29 ; 16,17.5 16.3,17.2 ; R73.2 v3(37.7,58.9) ; Q4.12 29.8,57.8 Q4.13 ; IC1.17 7.1,17.6 7,17.5 ; IC4.17 34.1,17.6 34,17.5 ; 25,17.5 IC3.29 ; 25,17.5 25.1,17.6 IC3.17 ; 25,17.5 25.4,17.1 ; 9.2,57.4 Q6.11 7.8,57.4 Q6.13 ; 9.2,57.4 v3(9.3,57.3) 9.4,57.4 Q8.6 10.7,57.4 Q8.13 ; 9.2,57.4 8.8,57.8 Q6.12 7.8,57.8 Q6.13 ; v3(12.5,57.4) Q7.6 14.1,57.4 Q7.13 ; v3(12.5,57.4) 12.1,57.8 Q8.12 11.1,57.8 Q8.13 ; v3(12.5,57.4) Q8.11 11.1,57.4 Q8.13 ; v3(27.5,57.4) 27.1,57.8 Q5.12 25.7,57.8 Q5.13 ; v3(27.5,57.4) Q4.6 29.4,57.4 Q4.13 ; v3(27.5,57.4) Q5.11 25.7,57.4 Q5.13 ; Q6.13 7.4,57.4 Q6.6 6.2,57.4 v3(6,57.2) ; 34.3,17.2 34,17.5 ; 34.3,17.2 IC4.16 ; 34.3,17.2 34.7,16.8 IC4.15 35.52,16.8 ; 34,17.5 IC4.29 ; IC3.15 25.7,16.8 25.4,17.1 ; Q5.13 25.3,57.4 Q5.6 v3(23.3,57.4) ; Q1.13 18.2,57.4 Q1.11 v3(19.7,57.4) ; Q1.13 18.2,57.8 Q1.12 19.4,57.8 19.7,57.5 v3(19.7,57.4) ; Q1.13 17.8,57.4 Q1.6 v3(16.3,57.4) ; 34.7,57.4 Q2.11 33.3,57.4 33.2,57.5 ; Q4.13 29.8,57.4 Q4.11 31,57.4 v3(31.2,57.2) 31.77,57.2 31.97,57.4 Q2.6 33.1,57.4 33.2,57.5 ; Q7.13 14.5,57.4 Q7.11 v3(16.3,57.4) ; Q7.13 14.5,57.8 Q7.12 15.9,57.8 v3(16.3,57.4) ; IC2.15 16.7,16.8 16.3,17.2 ; Q2.13 33.2,57.5 ; 33.2,57.5 33.5,57.8 Q2.12 34.7,57.8 v3(35,57.5) ; 16.3,17.2 IC2.16 ; 7,17.5 IC1.29 ; J2.9 19.36,7.42
  TOP w0.25: J1.1 27.07,53.47 27.4,53.8 ; v3(34.2,65.5) J4.5 v3(34.2,68.2) ; J4.42 v3(19.4,59.8) ; J3.40 12.93,28.03 12.9,28 ; v3(27.5,59.6) 27.4,59.7 J4.22 ; J1.40 31.13,28.03 31.1,28 ; J4.76 5.8,60 v3(5.65,59.85) ; v3(12.6,65.4) J4.59 12.6,68.2 ; J1.2 31.04,53.06 30.3,53.8 ; J1.39 27.07,28.03 27.1,28 ; 8.9,28 8.87,28.03 J3.39 ; J3.2 12.93,53.73 13,53.8 ; 8.9,53.9 8.87,53.87 J3.1
  TOP w0.3: J3.27 4.2,36.55 ; 4.2,36.55 3.9,36.26 C25.1 C27.1 C29.1 C31.1 C99.1 3.9,29.6 4.56,28.93 J3.39 ; 4.2,36.55 v3(4,36.55) 4,37 3.9,37.1 C23.1 C21.1 C19.1 C17.1 C15.1 C13.1 3.9,44.99 4.36,45.45 ; J1.39 23.72,28.93 23.56,29.1 v3(23,29.1) 22.44,29.1 22.1,29.44 C72.1 C68.1 C64.1 C60.1 C56.1 22.1,35.94 22.11,35.95 22.11,36.16 v3(22.5,36.55) ; v3(9.7,13.6) v3(9.7,14.4) ; 35.8,45.4 34.1,45.4 34.05,45.45 J1.14 ; 35.8,45.4 36.1,45.7 C57.1 C53.1 C49.1 C45.1 C39.1 36.1,52.4 36,52.5 v3(36,53.1) 35.97,53.06 J1.2 ; 35.8,45.4 v3(35.9,45.4) ; 35.8,45.4 36.1,45.1 C61.1 C65.1 C69.1 C42.1 C46.1 C50.1 36.1,37.14 35.76,36.8 ; 35.76,36.8 36.1,36.46 C54.1 C58.1 C62.1 C66.1 C70.1 36.1,29.34 35.76,29 v3(35.2,29) 32.87,29 32.81,28.93 J1.40 ; 35.76,36.8 35.56,36.6 v3(35.2,36.6) 34.44,36.6 34.4,36.55 J1.28 ; C145.1 4.14,8.7 3.9,8.46 3.9,8.4 ; 22.64,45.45 v3(22.6,45.4) 22.1,44.9 C63.1 C67.1 C71.1 C44.1 C48.1 C52.1 22.1,36.7 22.25,36.55 v3(22.5,36.55) ; 22.64,45.45 22.1,45.99 C59.1 C55.1 C51.1 C47.1 C43.1 22.1,52.5 22.4,52.8 v3(22.9,52.8) 23.8,52.8 24.07,53.06 J1.1 ; 22.64,45.45 J1.13 ; v3(3.9,4.8) 4.2,4.5 C146.1 ; v3(19.4,8.9) 19.8,9.3 v3(19.8,9.5) ; J3.13 4.36,45.45 ; 4.36,45.45 v3(4.3,45.45) 3.91,45.84 3.91,45.89 3.9,45.9 C11.1 C9.1 C7.1 C5.1 C3.1 3.9,52.6 4.37,53.06 J3.1 9.9,53.06 10.46,53.63 10.53,53.63 10.6,53.7 ; v3(17.55,36.55) 17.6,36.55 17.9,36.85 C22.1 C20.1 C18.1 C16.1 C14.1 C12.1 17.9,44.99 17.45,45.45 ; v3(17.55,36.55) 17.9,36.2 C24.1 C26.1 C28.1 C30.1 C32.1 17.9,29.6 17.9,29.6 17.9,29.2 17.6,28.9 v3(17,28.9) 16.44,28.9 16.41,28.93 J3.40 ; v3(17.55,36.55) 16.99,36.55 16.99,36.55 J3.28 ; J3.14 17.45,45.45 ; 17.45,45.45 17.9,45.9 C10.1 C8.1 C6.1 C4.1 C2.1 ; C2.1 17.9,51.9 ; C2.1 17.91,51.81 17.91,52.59 17.7,52.8 v3(17.1,52.8) 16.84,53.06 J3.2 11.9,53.06 11.2,53.77 11.2,53.8 ; v3(3.9,6.2) 4.2,5.9 C144.1 ; C143.1 4.2,7.3 3.9,7.6 v3(3.9,7.9) ; v3(22.5,36.55) J1.27 ; v3(19.36,1.7) v3(19.36,2.8) ; v3(27.7,13.4) v3(27.7,14.4)
  TOP w0.4: C41.1 v3(36.9,14.4) ; J2.9 v3(19.36,2.8) ; C36.1 11.27,22.03 v3(11.2,22.1) ; C34.1 v3(18.7,14.4) ; 19.36,7.42 19.36,8.87 v3(19.4,8.9) ; C40.1 v3(27.7,14.4) ; C37.1 v3(28.7,22.03) ; C35.1 v3(9.7,14.4) ; C33.1 v3(20.09,22.03) ; C38.1 v3(2.8,22.84) ; R74.1 v3(22.81,10.4)
  TOP w0.45: 2.6,67 TP4.1 3.9,68.3 ; 36.6,3.3 TP1.1 35.3,2 ; TP2.1 4.7,2 ; TP2.1 3.4,3.3 ; TP2.1 2.1,2 ; 37.4,67 TP3.1 36.1,68.3
  TOP w0.5: 4.8,8.02 C145.1 4.8,9.4 v3(4.7,9.5) ; 4.8,8.02 4.02,8.02 v3(3.9,7.9) 3.9,8.4 ; 4.8,8.02 C143.1 4.8,6.68 ; v3(34.5,6.1) 34.1,5.7 C101.1 ; C100.1 34.2,7.3 v3(34.5,7.6) ; C100.1 C102.1 33.8,9.1 v3(34.5,9.1) ; C100.1 C101.1 ; v3(2.5,56.5) C1.1 C98.1 v3(2.5,59.4) ; 4.8,6.68 4.42,6.68 ; 4.8,6.68 C144.1 4.8,5.21 ; 4.8,5.21 4.31,5.21 ; 4.8,5.21 C146.1 v3(4.8,3.4) ; C101.1 C142.1 ; C142.1 34,4.1 34.4,4.5 v3(34.5,4.5) ; C142.1 v3(33.5,2.9)
  LAYER_1 w0.45: 1.3,68.3 TP4.1 ; TP4.1 3.9,68.3 ; TP4.1 2.6,67 ; TP3.1 38.7,68.3 ; TP3.1 37.4,67 ; TP3.1 36.1,68.3 ; 36.6,0.7 TP1.1 ; TP1.1 36.6,3.3 ; TP1.1 35.3,2 ; TP1.1 37.9,2 ; TP2.1 3.4,3.3 ; TP2.1 3.4,0.7 ; TP2.1 2.1,2 ; TP2.1 4.7,2
  LAYER_3 w0.45: 37.4,67 TP3.1 ; TP3.1 36.1,68.3 ; TP3.1 38.7,68.3 ; 1.3,68.3 TP4.1 ; TP4.1 3.9,68.3 ; TP4.1 2.6,67 ; 36.6,0.7 TP1.1 ; TP1.1 35.3,2 ; TP1.1 37.9,2 ; TP1.1 36.6,3.3 ; 2.1,2 TP2.1 ; TP2.1 4.7,2 ; TP2.1 3.4,0.7 ; TP2.1 3.4,3.3
  LAYER_5 w0.45: 2.1,2 TP2.1 ; TP2.1 4.7,2 ; TP2.1 3.4,0.7 ; TP2.1 3.4,3.3 ; 37.4,67 TP3.1 ; TP3.1 38.7,68.3 ; TP3.1 36.1,68.3 ; 35.3,2 TP1.1 ; TP1.1 37.9,2 ; TP1.1 36.6,3.3 ; TP1.1 36.6,0.7 ; TP4.1 3.9,68.3 ; TP4.1 1.3,68.3 ; TP4.1 2.6,67
  LAYER_7 w0.45: 3.4,0.7 TP2.1 ; TP2.1 4.7,2 ; TP2.1 2.1,2 ; TP2.1 3.4,3.3 ; 36.6,0.7 TP1.1 ; TP1.1 36.6,3.3 ; TP1.1 37.9,2 ; TP1.1 35.3,2 ; 2.6,67 TP4.1 ; TP4.1 1.3,68.3 ; TP4.1 3.9,68.3 ; 36.1,68.3 TP3.1 ; TP3.1 37.4,67 ; TP3.1 38.7,68.3
  BOTTOM w0.45: 35.3,2 TP1.1 ; TP1.1 36.6,0.7 ; TP1.1 36.6,3.3 ; TP1.1 37.9,2 ; 3.9,68.3 TP4.1 2.6,67 ; 2.1,2 TP2.1 ; TP2.1 4.7,2 ; TP2.1 3.4,3.3 ; TP2.1 3.4,0.7 ; 37.4,67 TP3.1 36.1,68.3
  vias: v3(1.8,15.7) v3(2.5,55.5) v3(2.6,66.5) v3(3.3,59.8) v3(3.4,53) v3(4.4,53) v3(4.6,28.9) v3(4.8,36.5) v3(4.9,28.1) v3(5,63.6) v3(5.2,45.4) v3(5.6,17.4) v3(7.5,19) v3(7.8,68.7) v3(10.9,68.7) v3(10.9,28.1) v3(12.6,68.5) v3(14.2,68.7) v3(14.5,17.2) v3(16.3,18.7) v3(17.4,68.7) v3(17.4,45.5) v3(19.6,45.7) v3(20,59.5) v3(20.4,36.4) v3(21.3,45.4) v3(21.4,68.7) v3(23.6,17.2) v3(24.9,68.7) v3(25.4,18.8) v3(28.6,68.7) v3(29,53.7) v3(31.8,68.7) v3(32.7,17.4) v3(34.4,18.9) v3(35.2,28.1) v3(37.5,66.6) v3(37.7,59.9)
/LD: length 5.5
  TOP w0.4: R68.2 20.6,11.27 18.09,8.77 18.09,7.42
ALCOR_IN0: length 2.4
  TOP w0.25: J3.4 C108.1
ALCOR_IN1: length 2.4
  TOP w0.25: J3.3 C109.1
ALCOR_IN2: length 2.4
  TOP w0.25: J3.6 C110.1
ALCOR_IN3: length 2.4
  TOP w0.25: J3.5 7.06,50.52 7.05,50.53 C111.1
ALCOR_IN4: length 2.4
  TOP w0.25: J3.8 C112.1
ALCOR_IN5: length 2.4
  TOP w0.25: J3.7 C113.1
ALCOR_IN6: length 2.4
  TOP w0.25: J3.10 C114.1
ALCOR_IN7: length 2.4
  TOP w0.25: J3.9 C115.1
ALCOR_IN8: length 2.4
  TOP w0.25: J3.12 C116.1
ALCOR_IN9: length 2.4
  TOP w0.25: J3.11 C117.1
ALCOR_IN10: length 2.4
  TOP w0.25: J3.16 C118.1
ALCOR_IN11: length 2.4
  TOP w0.25: J3.15 C119.1
ALCOR_IN12: length 2.4
  TOP w0.25: J3.18 C120.1
ALCOR_IN13: length 2.4
  TOP w0.25: J3.17 C121.1
ALCOR_IN14: length 2.4
  TOP w0.25: J3.20 C122.1
ALCOR_IN15: length 2.4
  TOP w0.25: J3.19 C123.1
ALCOR_IN16: length 2.4
  TOP w0.25: J3.22 C124.1
ALCOR_IN17: length 2.4
  TOP w0.25: J3.21 C125.1
ALCOR_IN18: length 2.4
  TOP w0.25: J3.24 C126.1
ALCOR_IN19: length 2.4
  TOP w0.25: J3.23 C127.1
ALCOR_IN20: length 2.4
  TOP w0.25: J3.26 C128.1
ALCOR_IN21: length 2.4
  TOP w0.25: J3.25 C129.1
ALCOR_IN22: length 2.4
  TOP w0.25: J3.30 C130.1
ALCOR_IN23: length 2.4
  TOP w0.25: J3.29 C131.1
ALCOR_IN24: length 2.4
  TOP w0.25: J3.32 C132.1
ALCOR_IN25: length 2.4
  TOP w0.25: J3.31 C133.1
ALCOR_IN26: length 2.4
  TOP w0.25: J3.34 C134.1
ALCOR_IN27: length 2.4
  TOP w0.25: J3.33 C135.1
ALCOR_IN28: length 2.4
  TOP w0.25: J3.36 C136.1
ALCOR_IN29: length 2.4
  TOP w0.25: J3.35 C137.1
ALCOR_IN30: length 2.4
  TOP w0.25: J3.38 C138.1
ALCOR_IN31: length 2.4
  TOP w0.25: J3.37 C139.1
ALCOR_IN32: length 2.4
  TOP w0.25: J1.4 C73.1
ALCOR_IN33: length 2.4
  TOP w0.25: J1.3 C74.1
ALCOR_IN34: length 2.4
  TOP w0.25: J1.6 C75.1
ALCOR_IN35: length 2.4
  TOP w0.25: J1.5 C76.1
ALCOR_IN36: length 2.4
  TOP w0.25: J1.8 C77.1
ALCOR_IN37: length 2.4
  TOP w0.25: J1.7 C78.1
ALCOR_IN38: length 2.4
  TOP w0.25: J1.10 C79.1
ALCOR_IN39: length 2.4
  TOP w0.25: J1.9 C80.1
ALCOR_IN40: length 2.4
  TOP w0.25: J1.12 C81.1
ALCOR_IN41: length 2.4
  TOP w0.25: J1.11 C82.1
ALCOR_IN42: length 2.4
  TOP w0.25: J1.16 C83.1
ALCOR_IN43: length 2.4
  TOP w0.25: J1.15 C84.1
ALCOR_IN44: length 2.4
  TOP w0.25: J1.18 C85.1
ALCOR_IN45: length 2.4
  TOP w0.25: J1.17 C86.1
ALCOR_IN46: length 2.4
  TOP w0.25: J1.20 C87.1
ALCOR_IN47: length 2.4
  TOP w0.25: J1.19 C88.1
ALCOR_IN48: length 2.4
  TOP w0.25: J1.22 C89.1
ALCOR_IN49: length 2.4
  TOP w0.25: J1.21 C90.1
ALCOR_IN50: length 2.4
  TOP w0.25: J1.24 C91.1
ALCOR_IN51: length 2.4
  TOP w0.25: J1.23 C92.1
ALCOR_IN52: length 2.4
  TOP w0.25: J1.26 C93.1
ALCOR_IN53: length 2.4
  TOP w0.25: J1.25 C94.1
ALCOR_IN54: length 2.4
  TOP w0.25: J1.30 C95.1
ALCOR_IN55: length 2.4
  TOP w0.25: J1.29 C96.1
ALCOR_IN56: length 2.4
  TOP w0.25: J1.32 C97.1
ALCOR_IN57: length 2.4
  TOP w0.25: J1.31 C103.1
ALCOR_IN58: length 2.4
  TOP w0.25: J1.34 C104.1
ALCOR_IN59: length 2.4
  TOP w0.25: J1.33 C105.1
ALCOR_IN60: length 2.4
  TOP w0.25: C106.1 32.95,31.47 32.94,31.48 J1.36
ALCOR_IN61: length 2.4
  TOP w0.25: J1.35 C107.1
ALCOR_IN62: length 2.4
  TOP w0.25: J1.38 C140.1
ALCOR_IN63: length 2.4
  TOP w0.25: C141.1 J1.37
ANNEALING_ON: length 69
  TOP w0.3: v1(20.6,2.8) 20.64,2.83 20.64,4.38 ; v1(37.7,55.7) R75.2
  LAYER_2 w0.3: v1(37.7,55.7) 37.7,55.2 37,54.5 37,28.8 38.1,27.7 38.1,10.8 37.1,9.8 27.6,9.8 v1(20.6,2.8)
DIN: length 22.3
  TOP w0.4: v1(16.8,2.7) 16.8,2.8 16.82,2.83 J2.5
  TOP w0.5: R70.2 2.5,11.9 v1(3,11.4)
  LAYER_6 w0.5: v1(3,11.4) 3.9,10.5 10.5,10.5 16.8,4.2 v1(16.8,2.7)
DOUT: length 25.2
  TOP w0.4: R71.2 36.8,11.8 v1(36.8,11.2) ; 18.09,4.38 v1(18.09,2.7)
  LAYER_2 w0.4: v1(36.8,11.2) 36,10.4 26.7,10.4 22.3,6 20.5,6 18.1,3.6 18.1,3.31 18.09,3.3 v1(18.09,2.7)
EN_ANNEALING: length 46.1
  TOP w0.2: v1(12.6,58.2) 13.05,58.2 Q7.5 ; Q3.5 20.5,57.8 v1(19.9,58.4) ; Q4.5 28.2,57.8 v1(27.8,58.2) ; Q8.5 9.7,57.8 9.3,58.2 v1(9.3,58.3) ; v1(16.5,58.4) 16.5,58.1 16.8,57.8 Q1.5 ; R75.1 R73.1 v1(35.9,58) ; v1(5.8,58.1) 5.9,58.1 6.2,57.8 Q6.5 ; Q2.5 31.5,57.8 31.2,58.1 v1(31.2,58.2) ; v1(23.6,58.3) 23.6,58.2 24,57.8 Q5.5
  TOP w0.5: C98.2 4.75,58.5 5.15,58.1 ; 5.15,58.1 v1(5.8,58.1) ; 5.15,58.1 4.35,57.3 C1.2
  LAYER_4 w0.3: v1(35.9,58) 35.4,58 35.3,58.1 31.85,58.1 31.75,58.2 v1(31.2,58.2) v1(27.8,58.2) 23.8,58.2 23.7,58.3 v1(23.6,58.3) 23.05,58.3 22.95,58.4 v1(19.9,58.4) v1(16.5,58.4) 16,58.4 15.9,58.3 13.2,58.3 13.1,58.2 v1(12.6,58.2) 12.1,58.2 12,58.3 v1(9.3,58.3) 6.5,58.3 6.3,58.1 v1(5.8,58.1)
LM73SCL: length 60.2
  TOP w0.2: J4.40 v1(20.2,62.5)
  TOP w0.4: 15.55,7.42 v1(15.55,8.9) 15.55,9.35 15.7,9.5 R6.2
  LAYER_6 w0.25: v1(15.55,8.9) 15.93,9.27 15.93,9.27 18.3,11.64 18.3,13.3 18,13.6 18,19.5 19.4,20.9 19.4,25.8 19,26.2 19,52.9 20,53.9 20,56.2 20.8,57 20.8,59.8 20.2,60.4 v1(20.2,62.5)
LM73SDA: length 72.1
  TOP w0.2: J4.41 v1(19.8,65.5)
  TOP w0.4: R7.2 14.4,9.6 v1(14.43,9.6) ; v1(15.55,2.8) J2.3
  LAYER_2 w0.4: v1(14.43,9.6) 14.43,8.07 15.55,6.95 v1(15.55,2.8)
  LAYER_6 w0.25: v1(19.8,65.5) 19.8,63.1 19.4,62.7 19.4,61 18.8,60.4 18.8,57.3 19.6,56.5 19.6,54.1 18.3,52.8 18.3,25.6 16.8,24.1 16.8,20.9 11.9,16 11.9,11.5
  LAYER_6 w0.3: v1(14.43,9.6) 14.04,9.99 13.41,9.99 11.9,11.5
LM73VCC: length 64.5
  TOP w0.2: J4.39 v1(20.6,65)
  TOP w0.4: v1(16.7,10.9) 16.4,10.6 R6.1 R7.1 R5.2
  LAYER_2 w0.3: v1(16.7,10.9) 17.8,10.9 18.3,11.4 18.3,12.8 17.7,13.4 17.7,21.5 19.4,23.2 19.4,25.8 18.8,26.4 18.8,52.6 19.7,53.5 19.7,56.3 18.82,57.18 18.82,60.42 19.4,61 19.4,63 20.6,64.2 v1(20.6,65)
SCK: length 5.5
  TOP w0.4: R69.2 19.2,11.27 16.82,8.9 16.82,7.42
SIPMOUT0: length 19.4
  TOP w0.2: J4.43 v1(19,65) ; v1(19,55.8) 18.6,56.2 Q1.10
  TOP w0.25: C108.2 v1(17.1,51.8)
  LAYER_6 w0.2: v1(17.1,51.8) 17.83,52.52 17.83,53.33 19,54.5 v1(19,55.8) 18.2,56.6 18.2,62.1 19.2,63.1 19.2,64 19,64.2 v1(19,65)
  BOTTOM w0.25: R1.2 17.89,51.8 v1(17.1,51.8)
SIPMOUT1: length 19.8
  TOP w0.2: Q6.7 7,56.27 6.63,55.9 v1(6.4,55.9) ; v1(6.2,65.5) J4.75
  TOP w0.25: C109.2 v1(4.79,51.8)
  LAYER_2 w0.2: v1(4.79,51.8) 5.15,52.15 5.15,55.9 ; 5.15,55.9 5,56.05 5,60.6 5.8,61.4 5.8,64.1 6.2,64.5 v1(6.2,65.5) ; 5.15,55.9 v1(6.4,55.9)
  BOTTOM w0.25: v1(4.79,51.8) R8.2
SIPMOUT2: length 20.5
  TOP w0.2: v1(18.6,63.4) J4.44 Q1.1
  TOP w0.25: C110.2 v1(17,50.52)
  LAYER_8 w0.2: v1(17,50.52) 18.8,52.33 18.8,55.1 18.3,55.6 18.3,60.09 18.6,60.39 v1(18.6,63.4)
  BOTTOM w0.25: v1(17,50.52) R12.2
SIPMOUT3: length 18.7
  TOP w0.2: Q6.4 7,59.4 6.6,59.8 J4.74 v1(6.6,62.43)
  TOP w0.25: v1(4.7,50.52) 4.9,50.52 4.91,50.53 C111.2
  LAYER_6 w0.2: v1(4.7,50.52) 5.4,51.23 5.4,53.7 5.1,54 5.1,58.3 6.6,59.8 v1(6.6,62.43)
  BOTTOM w0.25: v1(4.7,50.52) 3.91,50.52 R16.2
SIPMOUT4: length 22.3
  TOP w0.2: J4.45 v1(18.2,65.5) ; Q1.9 18.2,55.7 18,55.5 v1(18,55)
  TOP w0.25: C112.2 v1(17,49.26)
  LAYER_2 w0.2: v1(18.2,65.5) 18.2,64.4 17.8,64 17.8,63.3 18.6,62.5 18.6,61.5 17.84,60.74 17.84,55.66 18,55.5 v1(18,55) 18,50.26 v1(17,49.26)
  BOTTOM w0.25: v1(17,49.26) R20.2
SIPMOUT5: length 23.8
  TOP w0.2: Q6.8 7.4,55.7 v1(5.95,54.25) ; v1(7,65) J4.73
  TOP w0.25: C113.2 v1(4.79,49.26)
  LAYER_8 w0.2: v1(7,65) 6.64,64.64 6.64,63.27 7.4,62.52 7.4,55.7 v1(5.95,54.25) 5.95,50.41 v1(4.79,49.26)
  BOTTOM w0.25: v1(4.79,49.26) R24.2
SIPMOUT6: length 21.7
  TOP w0.2: Q1.2 18.2,59.7 17.8,60.1 J4.46 v1(17.8,62.5)
  TOP w0.25: C114.2 v1(17,47.98)
  LAYER_2 w0.2: v1(17.8,62.5) 17.8,61.8 17.3,61.3 17.3,55.3 16.75,54.75 16.75,53.45 16.2,52.9 16.2,48.2 16.41,47.98 v1(17,47.98)
  BOTTOM w0.25: v1(17,47.98) R28.2
SIPMOUT7: length 23
  TOP w0.2: v1(7.4,63.4) J4.72 Q6.3
  TOP w0.25: C115.2 v1(4.79,47.98)
  LAYER_6 w0.2: v1(4.79,47.98) 6.75,49.94 6.75,55.25 7.4,55.9 v1(7.4,63.4)
  BOTTOM w0.25: v1(4.79,47.98) R32.2
SIPMOUT8: length 25.7
  TOP w0.2: v1(17.4,54.4) 17.4,55.6 17.8,56 Q1.8 ; J4.47 v1(17.4,65)
  TOP w0.25: C116.2 v1(17.1,46.72)
  LAYER_6 w0.2: v1(17.4,65) 17.4,64.3 17.8,63.9 17.8,63.3 17,62.5 17,61.6 17.3,61.3 17.3,55.01 17.4,54.91 v1(17.4,54.4) 16.3,53.3 16.3,47.52 v1(17.1,46.72)
  BOTTOM w0.25: v1(17.1,46.72) R36.2
SIPMOUT9: length 25.7
  TOP w0.2: J4.71 v1(7.8,65.5) ; Q6.9 7.8,55.06 7.54,54.8 v1(7.4,54.8)
  TOP w0.25: C117.2 v1(4.8,46.72)
  LAYER_2 w0.2: v1(4.8,46.72) 5.31,46.72 6.7,48.1 6.7,54.1 v1(7.4,54.8) 7.4,62.5 8.1,63.2 8.1,64.1 7.8,64.4 v1(7.8,65.5)
  BOTTOM w0.25: v1(4.8,46.72) R40.2
SIPMOUT10: length 27.5
  TOP w0.2: v1(17,63.4) J4.48 17,59.93 17.8,59.13 Q1.3
  TOP w0.25: C118.2 v1(17.1,44.17)
  LAYER_8 w0.2: v1(17,63.4) 17,60.4 17.3,60.1 17.3,55.5 16.7,54.9 16.7,54.4 16,53.7 16,44.77 16.6,44.17 v1(17.1,44.17)
  BOTTOM w0.25: v1(17.1,44.17) R44.2
SIPMOUT11: length 25.7
  TOP w0.2: Q6.2 7.8,59.49 8.2,59.89 J4.70 v1(8.2,62.43)
  TOP w0.25: C119.2 v1(4.8,44.17)
  LAYER_2 w0.2: v1(4.8,44.17) 5.3,44.17 7.4,46.27 7.4,53.4 8.2,54.2 v1(8.2,62.43)
  BOTTOM w0.25: v1(4.8,44.17) R48.2
SIPMOUT12: length 29.4
  TOP w0.2: Q1.7 17.4,56.5 17.1,56.2 v1(16.7,56.2) ; J4.49 v1(16.6,65.5)
  TOP w0.25: C120.2 v1(17,42.91)
  LAYER_2 w0.2: v1(16.6,65.5) 16.6,64.4 16.2,64 16.2,63.3 16.8,62.7 16.8,61.5 15.7,60.4 15.7,57.2 v1(16.7,56.2) 16.7,55.6 16.35,55.25 16.35,53.85 15.4,52.9 15.4,44 16.49,42.91 v1(17,42.91)
  BOTTOM w0.25: v1(17,42.91) R52.2
SIPMOUT13: length 29.9
  TOP w0.2: v1(9,56) 8.47,56 8.2,56.27 Q6.10 ; J4.69 v1(8.6,65)
  TOP w0.25: C121.2 v1(4.8,42.91)
  LAYER_6 w0.2: v1(8.6,65) 8.6,64.4 8.2,64 8.2,63.3 9,62.5 9,61.4 8.5,60.9 8.5,57.1 9,56.6 v1(9,56) 8.2,55.2 8.2,45.8 5.3,42.91 v1(4.8,42.91)
  BOTTOM w0.25: v1(4.8,42.91) R56.2
SIPMOUT14: length 28.7
  TOP w0.2: v1(16.2,62.5) J4.50 16.2,59.8 17.4,58.6 Q1.4
  TOP w0.25: C122.2 v1(17,41.63)
  LAYER_6 w0.2: v1(16.2,62.5) 16.2,59.4 15.7,58.9 15.7,56.4 16.3,55.8 16.3,54.2 15.5,53.4 15.5,42.63 16.5,41.63 v1(17,41.63)
  BOTTOM w0.25: v1(17,41.63) R60.2
SIPMOUT15: length 30.7
  TOP w0.2: v1(9,63.4) J4.68 9,59.9 8.2,59.1 Q6.1
  TOP w0.25: C123.2 v1(4.7,41.63)
  LAYER_8 w0.2: v1(4.7,41.63) 5.2,41.63 8.1,44.53 8.1,58.9 9,59.8 v1(9,63.4)
  BOTTOM w0.25: v1(4.7,41.63) R64.2
SIPMOUT16: length 33.2
  TOP w0.2: J4.51 v1(15.8,65) ; Q7.10 14.9,56.5 15.7,55.7 v1(15.7,54.6)
  TOP w0.25: C124.2 v1(17,40.37)
  LAYER_2 w0.2: v1(17,40.37) 16.34,40.37 14.8,41.9 14.8,53.2 15.7,54.1 v1(15.7,54.6)
  LAYER_6 w0.2: v1(15.8,65) 15.8,64.49 16.2,64.09 16.2,63.3 15.4,62.5 15.4,59.8 14.9,59.3 14.9,56.5 15.7,55.7 v1(15.7,54.6)
  BOTTOM w0.25: v1(17,40.37) R3.2
SIPMOUT17: length 33.9
  TOP w0.2: J4.67 v1(9.4,65.5) ; Q8.7 10.3,56 v1(9.2,54.9)
  TOP w0.25: C125.2 v1(4.7,40.37)
  LAYER_2 w0.2: v1(9.4,65.5) 9.4,64.2 9.7,63.9 9.7,63.2 9,62.5 9,59.5 10.1,58.4 10.1,55.8 v1(9.2,54.9) 9.2,54.2 8.1,53.1 8.1,43.1 5.37,40.37 v1(4.7,40.37)
  BOTTOM w0.25: v1(4.7,40.37) R10.2
SIPMOUT18: length 32.4
  TOP w0.2: Q7.1 14.9,59.44 15.4,59.94 J4.52 v1(15.4,63.4)
  TOP w0.25: C126.2 v1(17,39.09)
  LAYER_8 w0.2: v1(17,39.09) 16.41,39.09 15.05,40.45 15.05,54.95 15.4,55.3 v1(15.4,63.4)
  BOTTOM w0.25: v1(17,39.09) R14.2
SIPMOUT19: length 31.7
  TOP w0.2: v1(9.8,62.43) J4.66 9.8,59.7 10.3,59.2 Q8.4
  TOP w0.25: C127.2 v1(4.8,39.09)
  LAYER_6 w0.2: v1(4.8,39.09) 5.31,39.09 8.9,42.69 8.9,53.5 9.9,54.5 9.9,56.5 10.1,56.7 10.1,58.9 9.8,59.2 v1(9.8,62.43)
  BOTTOM w0.25: v1(4.8,39.09) R18.2
SIPMOUT20: length 34.2
  TOP w0.2: J4.53 v1(15,65.5) ; Q7.9 14.5,55.9 14.7,55.7 v1(14.8,55.7)
  TOP w0.25: C128.2 v1(17,37.83)
  LAYER_2 w0.2: v1(17,37.83) 16.48,37.83 14,40.3 14,53.6 14.8,54.4 v1(14.8,55.7) 14.8,60.3 15.2,60.7 15.2,62.7 14.7,63.2 14.7,64.1 15,64.4 v1(15,65.5)
  BOTTOM w0.25: v1(17,37.83) R22.2
SIPMOUT21: length 35.6
  TOP w0.2: v1(10.5,55.2) 10.5,55.7 10.7,55.9 Q8.8 ; J4.65 v1(10.2,65)
  TOP w0.25: C129.2 v1(4.8,37.83)
  LAYER_6 w0.2: v1(10.2,65) 10.2,64.49 9.8,64.09 9.8,63.37 10.7,62.47 10.7,56.3 10.5,56.1 v1(10.5,55.2) 10.5,54.2 9.7,53.4 9.7,42.1 5.43,37.83 v1(4.8,37.83)
  BOTTOM w0.25: v1(4.8,37.83) R26.2
SIPMOUT22: length 35.2
  TOP w0.2: v1(14.6,62.5) J4.54 14.6,59.9 14.5,59.8 Q7.2
  TOP w0.25: C130.2 v1(17,35.28)
  LAYER_2 w0.2: v1(17,35.28) 16.5,35.28 13.4,38.38 13.4,55.1 14.1,55.8 14.1,60.8 14.6,61.3 v1(14.6,62.5)
  BOTTOM w0.25: v1(17,35.28) R30.2
SIPMOUT23: length 37.5
  TOP w0.2: Q8.3 10.7,59.9 10.6,60 J4.64 v1(10.6,63.4)
  TOP w0.25: C131.2 v1(4.8,35.28)
  LAYER_8 w0.2: v1(4.8,35.28) 5.48,35.28 8.9,38.7 8.9,53.6 9.9,54.6 9.9,55.7 10.6,56.4 v1(10.6,63.4)
  BOTTOM w0.25: v1(4.8,35.28) R34.2
SIPMOUT24: length 38.5
  TOP w0.2: Q7.8 v1(14.1,54.8) ; J4.55 v1(14.2,65)
  TOP w0.25: C132.2 v1(17,34.02)
  LAYER_6 w0.2: v1(17,34.02) 16.29,34.02 14.1,36.2 v1(14.1,54.8) 14.1,60.4 13.9,60.6 13.9,62.6 14.6,63.3 14.6,64 14.2,64.4 v1(14.2,65)
  BOTTOM w0.25: v1(17,34.02) R38.2
SIPMOUT25: length 39.4
  TOP w0.2: Q8.9 11.1,55.9 v1(11.3,55.7) ; J4.63 v1(11,65.5)
  TOP w0.25: C133.2 v1(4.8,34.02)
  LAYER_2 w0.2: v1(11,65.5) 11,64.45 11.4,64.05 11.4,63.37 10.6,62.57 10.6,59 10.9,58.7 10.9,56.1 v1(11.3,55.7) 11.3,55.2 8.8,52.7 8.8,37.3 5.52,34.02 v1(4.8,34.02)
  BOTTOM w0.25: v1(4.8,34.02) R42.2
SIPMOUT26: length 39.3
  TOP w0.2: Q7.3 14.1,59.7 13.8,60 J4.56 v1(13.8,63.4)
  TOP w0.25: C134.2 v1(17,32.74)
  LAYER_8 w0.2: v1(13.8,63.4) 13.8,62.9 13.53,62.62 13.53,35.58 16.36,32.74 v1(17,32.74)
  BOTTOM w0.25: v1(17,32.74) R46.2
SIPMOUT27: length 39.1
  TOP w0.2: Q8.2 11.1,59.8 11.4,60.1 J4.62 v1(11.4,62.43)
  TOP w0.25: C135.2 v1(4.8,32.74)
  LAYER_2 w0.2: v1(11.4,62.43) 11.4,60.9 11.7,60.6 11.7,56.8 12,56.5 12,55.2 9.6,52.8 9.6,36.7 5.64,32.74 v1(4.8,32.74)
  BOTTOM w0.25: v1(4.8,32.74) R50.2
SIPMOUT28: length 41.5
  TOP w0.2: v1(13.1,64.3) 13.1,64.8 13.4,65.1 J4.57 ; Q7.7 13.7,56.27 13.53,56.1 v1(12.9,56.1)
  TOP w0.25: C136.2 v1(17,31.48)
  LAYER_2 w0.2: v1(17,31.48) 16.5,31.48 12.4,35.57 12.4,53.6 12.9,54.1 v1(12.9,56.1) 12.9,56.7 13.3,57.1 13.3,61.2 13.8,61.7 13.8,62.5 13.1,63.2 v1(13.1,64.3)
  BOTTOM w0.25: v1(17,31.48) R54.2
SIPMOUT29: length 43.8
  TOP w0.2: Q8.10 11.5,56.5 12.1,55.9 v1(12.1,54.4) ; J4.61 v1(11.8,65)
  TOP w0.25: C137.2 v1(4.8,31.48)
  LAYER_6 w0.2: v1(11.8,65) 11.8,64.85 11.4,64.45 11.4,63.37 12.2,62.57 12.2,59.6 11.8,59.2 11.8,56.5 12.1,56.2 v1(12.1,54.4) 12.1,53.9 12.2,53.8 12.2,38.3 5.38,31.48 v1(4.8,31.48)
  BOTTOM w0.25: v1(4.8,31.48) R58.2
SIPMOUT30: length 40
  TOP w0.2: v1(13,62.43) J4.58 13,59.9 13.7,59.2 Q7.4
  TOP w0.25: C138.2 v1(17,30.2)
  LAYER_6 w0.2: v1(17,30.2) 16.5,30.2 13.5,33.2 13.5,59 13,59.5 v1(13,62.43)
  BOTTOM w0.25: v1(17,30.2) R62.2
SIPMOUT31: length 43.5
  TOP w0.2: Q8.1 11.5,59 12.2,59.7 J4.60 v1(12.2,63.4)
  TOP w0.25: C139.2 v1(4.8,30.2)
  LAYER_8 w0.2: v1(4.8,30.2) 5.4,30.2 9.73,34.53 9.73,53.03 11.9,55.2 11.9,59.9 12.2,60.2 v1(12.2,63.4)
  BOTTOM w0.25: v1(4.8,30.2) 3.91,30.2 R66.2
SIPMOUT32: length 16.9
  TOP w0.2: v1(33.8,62.5) J4.6 Q2.1
  TOP w0.25: C73.2 v1(35.2,51.8)
  LAYER_6 w0.2: v1(33.8,62.5) 33.8,57.9 35.2,56.5 v1(35.2,51.8)
  BOTTOM w0.25: v1(35.2,51.8) R72.2
SIPMOUT33: length 19.3
  TOP w0.2: Q3.4 J4.38 v1(21,63.4) ; C74.2 v1(22.97,51.8)
  LAYER_8 w0.2: v1(21,63.4) 21,61.2 22,60.2 22,52.26 22.47,51.8 v1(22.97,51.8)
  BOTTOM w0.2: v1(22.97,51.8) R83.2
SIPMOUT34: length 20.8
  TOP w0.2: Q2.10 33.8,56.17 34.07,55.9 v1(34.6,55.9) ; J4.7 v1(33.4,65)
  TOP w0.25: C75.2 v1(35.3,50.52)
  LAYER_6 w0.2: v1(33.4,65) 33.8,64.6 33.8,63.3 33,62.5 33,59.5 33.3,59.2 33.3,57.2 v1(34.6,55.9) 34.6,51.23 v1(35.3,50.52)
  BOTTOM w0.25: v1(35.3,50.52) R87.2
SIPMOUT35: length 21.4
  TOP w0.2: J4.37 v1(21.4,65.5) ; v1(20.7,55.2) 20.7,55.7 21,56 Q3.7
  TOP w0.25: C76.2 v1(23,50.52)
  LAYER_2 w0.2: v1(21.4,65.5) 21.4,64.4 21.8,64 21.8,63.3 21.2,62.7 21.2,56.7 20.7,56.2 v1(20.7,55.2)
  LAYER_8 w0.2: v1(23,50.52) 22.5,50.52 20.7,52.32 v1(20.7,55.2)
  BOTTOM w0.25: v1(23,50.52) R91.2
SIPMOUT36: length 22.1
  TOP w0.2: v1(33,63.4) J4.8 33,60.48 33.4,60.08 Q2.2
  TOP w0.25: C77.2 v1(35.2,49.26)
  LAYER_8 w0.2: v1(35.2,49.26) 34.64,49.26 34.3,49.6 34.3,55.3 33,56.6 v1(33,63.4)
  BOTTOM w0.25: v1(35.2,49.26) R95.2
SIPMOUT37: length 20.1
  TOP w0.2: v1(21.8,62.5) J4.36 21.8,60.1 21.4,59.7 Q3.3
  TOP w0.25: C78.2 v1(23,49.26)
  LAYER_2 w0.2: v1(21.8,62.5) 21.8,55.4 22.1,55.1 22.1,53.6 21.8,53.3 21.8,49.9 22.45,49.26 v1(23,49.26)
  BOTTOM w0.25: v1(23,49.26) R99.2
SIPMOUT38: length 23.8
  TOP w0.2: J4.9 v1(32.6,65.5) ; Q2.9 33.4,56.01 33.5,55.91 v1(33.5,55.2)
  TOP w0.25: C79.2 v1(35.3,47.98)
  LAYER_2 w0.2: v1(32.6,65.5) 32.6,64.4 32.2,64 32.2,63.3 33,62.5 33,61.7 33.5,61.2 v1(33.5,55.2) 33.5,49.2 34.7,48 34.78,48 34.79,47.98 v1(35.3,47.98)
  BOTTOM w0.25: v1(35.3,47.98) R103.2
